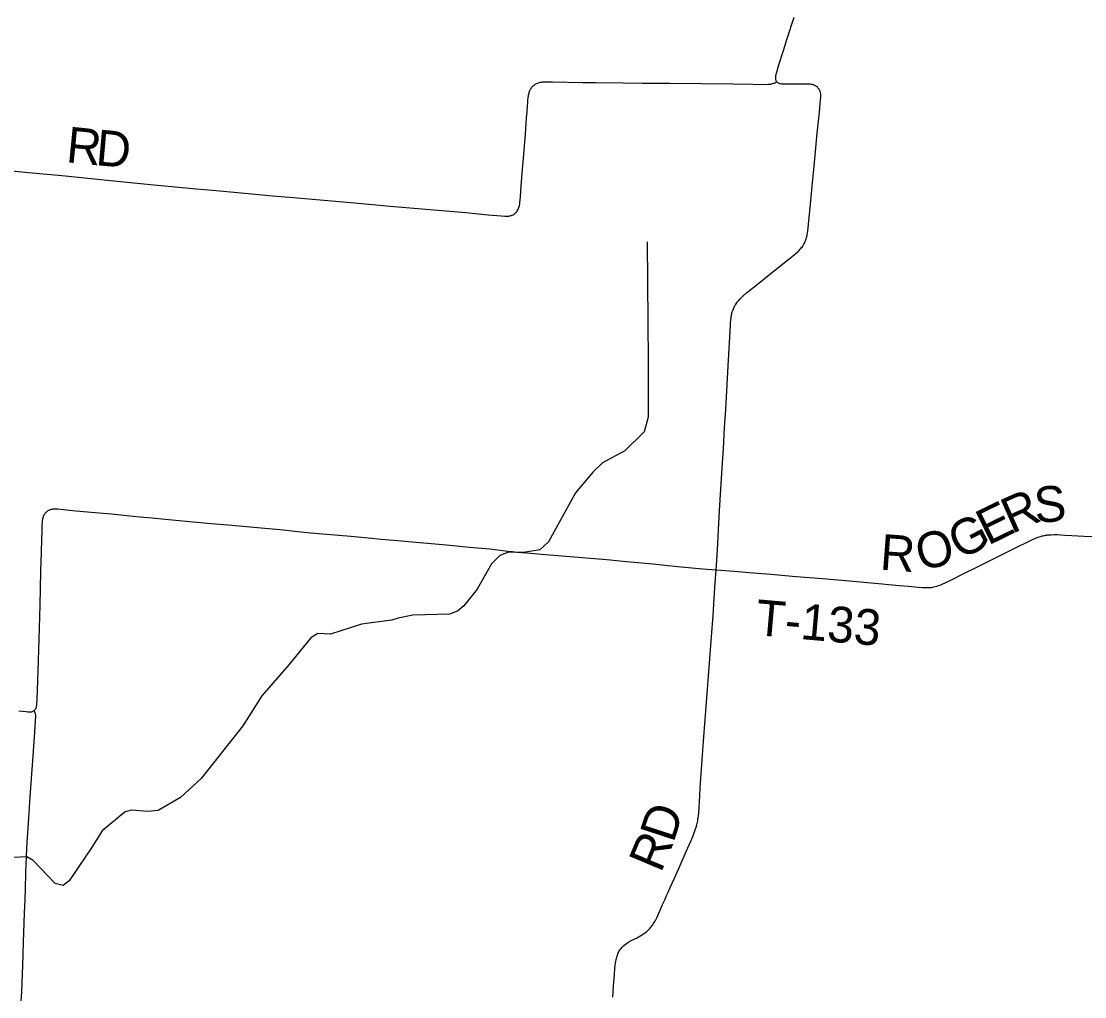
# Model space of a CAD drawing. Extents: x -49 to -8.2, y 9.4 to 23.5.
# Drawn here: x -43.371 to -42.527, y 19.456 to 20.23 of the extents above; entities that cross this region are included whole.
import ezdxf

# ---------------------------------------------------------------- set-up
doc = ezdxf.new("R2010")
doc.units = 0
for name, color, linetype in [('GM_X_County_Road', 7, 'Continuous'), ('GM_X_County_Road_Text', 7, 'Continuous'), ('GM_X_Major_River', 7, 'Continuous'), ('GM_X_Township_Road', 7, 'Continuous'), ('GM_X_Township_Road_Text', 7, 'Continuous')]:
    doc.layers.add(name, color=color, linetype=linetype)

msp = doc.modelspace()

# ---------------------------------------------------------------- linework, layer by layer
at = {"layer": 'GM_X_County_Road'}
for points in [[(-43.38957, 20.11204), (-43.36575, 20.10974), (-43.33915, 20.10727), (-43.29525, 20.10286), (-43.27947, 20.10135), (-43.26617, 20.10011), (-43.25194, 20.09874), (-43.23246, 20.0969), (-43.22596, 20.0963), (-43.2139, 20.09519), (-43.19689, 20.09352), (-43.1721, 20.09125), (-43.15852, 20.0901), (-43.13406, 20.08802), (-43.10404, 20.08536), (-43.07867, 20.08299), (-43.04709, 20.08036), (-43.0186, 20.07791), (-43.00066, 20.07628), (-42.99043, 20.07533), (-42.98763, 20.07512), (-42.98672, 20.07508), (-42.98578, 20.0751), (-42.98493, 20.07516), (-42.98425, 20.07524), (-42.98362, 20.07536), (-42.98296, 20.07551), (-42.98232, 20.07572), (-42.98158, 20.076), (-42.98101, 20.07628), (-42.98016, 20.07678), (-42.97946, 20.07731), (-42.97878, 20.07792), (-42.97837, 20.07837), (-42.97805, 20.07878), (-42.97761, 20.07937), (-42.97716, 20.08016), (-42.97673, 20.0811), (-42.97643, 20.0819), (-42.97618, 20.08274), (-42.97593, 20.08368), (-42.97572, 20.08472), (-42.97555, 20.08583), (-42.97516, 20.09018), (-42.97445, 20.09916), (-42.97343, 20.11249), (-42.97251, 20.12395), (-42.97124, 20.14006), (-42.97021, 20.15306), (-42.96985, 20.15771), (-42.9695, 20.16299), (-42.96939, 20.16486), (-42.96921, 20.16733), (-42.96903, 20.16891), (-42.96894, 20.16957), (-42.96884, 20.17023), (-42.96869, 20.17104), (-42.96849, 20.17202), (-42.96829, 20.17284), (-42.96809, 20.17346), (-42.9679, 20.17407), (-42.96763, 20.17475), (-42.96738, 20.17532), (-42.96705, 20.17592), (-42.96669, 20.17654), (-42.96627, 20.17713), (-42.9658, 20.17769), (-42.9653, 20.17821), (-42.96465, 20.17884), (-42.96409, 20.17929), (-42.96344, 20.17974), (-42.96287, 20.18008), (-42.96205, 20.18049), (-42.96128, 20.18079), (-42.9607, 20.181), (-42.95994, 20.18122), (-42.9592, 20.18139), (-42.95835, 20.18153), (-42.95758, 20.18163), (-42.95654, 20.1817), (-42.95531, 20.18174), (-42.94976, 20.18169), (-42.92615, 20.18116), (-42.91527, 20.18108), (-42.89352, 20.18091), (-42.8783, 20.18079), (-42.85655, 20.18062), (-42.83138, 20.18035), (-42.80653, 20.18007), (-42.79037, 20.17979), (-42.78167, 20.17971), (-42.77857, 20.17975), (-42.77764, 20.1798), (-42.77671, 20.17989), (-42.77608, 20.17999), (-42.77549, 20.18013), (-42.7749, 20.18032), (-42.77428, 20.18054), (-42.77369, 20.18077), (-42.77305, 20.18104), (-42.77232, 20.18139), (-42.77164, 20.18174)], [(-43.36132, 19.68272), (-43.36107, 19.68293), (-43.36074, 19.68321), (-43.36039, 19.68356), (-43.36008, 19.68395), (-43.35986, 19.68428), (-43.35965, 19.68463), (-43.3595, 19.685), (-43.35938, 19.68543), (-43.35929, 19.68584), (-43.35914, 19.68745), (-43.35894, 19.69181), (-43.3584, 19.70641), (-43.35785, 19.72256), (-43.35732, 19.73932), (-43.35654, 19.76635), (-43.35583, 19.79337), (-43.35531, 19.80858), (-43.355, 19.81852), (-43.35486, 19.82504), (-43.35477, 19.83032), (-43.35468, 19.83192), (-43.35455, 19.83321), (-43.35441, 19.83426), (-43.35424, 19.83522), (-43.35406, 19.83603), (-43.35387, 19.83662), (-43.35369, 19.83716), (-43.35348, 19.83767), (-43.35322, 19.83823), (-43.35291, 19.83874), (-43.35258, 19.83919), (-43.35219, 19.83966), (-43.3517, 19.8402), (-43.35124, 19.84059), (-43.35077, 19.84097), (-43.35026, 19.84133), (-43.34975, 19.84166), (-43.34929, 19.8419), (-43.34867, 19.84217), (-43.3481, 19.84236), (-43.3474, 19.84254), (-43.34664, 19.84266), (-43.34602, 19.84273), (-43.34528, 19.84278), (-43.34446, 19.84281), (-43.34343, 19.8428), (-43.34243, 19.84275), (-43.34035, 19.84256), (-43.33543, 19.84209), (-43.32824, 19.84137), (-43.31282, 19.83999), (-43.2998, 19.83876), (-43.28773, 19.83753), (-43.27752, 19.83655), (-43.26763, 19.8356), (-43.25712, 19.83455), (-43.24042, 19.83299), (-43.22072, 19.83124), (-43.20428, 19.8298), (-43.1896, 19.82849), (-43.1633, 19.82606), (-43.15183, 19.82491), (-43.14143, 19.82392), (-43.12878, 19.8228), (-43.10991, 19.82105), (-43.09599, 19.81978), (-43.08579, 19.81885), (-43.07249, 19.81766), (-43.05504, 19.81611), (-43.03387, 19.81422), (-43.01558, 19.81254), (-42.99935, 19.81102), (-42.98509, 19.80929), (-42.98141, 19.80888), (-42.97796, 19.80855), (-42.97, 19.80785), (-42.95836, 19.80692), (-42.92306, 19.80399), (-42.90666, 19.80252), (-42.89088, 19.80106), (-42.87015, 19.79912), (-42.85046, 19.79721), (-42.8304, 19.79523), (-42.81972, 19.79437)], [(-43.37331, 19.68243), (-43.36747, 19.6819), (-43.36611, 19.68177), (-43.365, 19.68169), (-43.36402, 19.68169), (-43.36353, 19.68175), (-43.36302, 19.68186), (-43.36257, 19.682), (-43.36216, 19.68218), (-43.36177, 19.68241), (-43.36132, 19.68272)]]:
    msp.add_lwpolyline(points, dxfattribs=at)
at = {"layer": 'GM_X_Major_River'}
msp.add_lwpolyline([(-42.87443, 20.05484), (-42.87369, 19.9595), (-42.87381, 19.91564), (-42.87688, 19.90393), (-42.89213, 19.88886), (-42.9101, 19.87935), (-42.91743, 19.87228), (-42.93138, 19.85547), (-42.95278, 19.8166), (-42.95972, 19.81028), (-42.97262, 19.80827), (-42.98473, 19.80833), (-42.99159, 19.80581), (-42.99815, 19.7991), (-43.00953, 19.77902), (-43.02019, 19.76575), (-43.025, 19.76167), (-43.03149, 19.75914), (-43.06063, 19.75841), (-43.07222, 19.75598), (-43.07736, 19.75457), (-43.10145, 19.75126), (-43.12582, 19.7434), (-43.13602, 19.7438), (-43.14158, 19.7405), (-43.15903, 19.71901), (-43.18052, 19.69457), (-43.19556, 19.67057), (-43.22855, 19.62889), (-43.24493, 19.61384), (-43.26273, 19.60357), (-43.27126, 19.60261), (-43.28373, 19.60381), (-43.28886, 19.60239), (-43.30732, 19.5872), (-43.31631, 19.57295), (-43.32021, 19.56714), (-43.33346, 19.54766), (-43.33827, 19.54396), (-43.34448, 19.5456), (-43.36208, 19.56381), (-43.36695, 19.56657), (-43.39289, 19.56538)], dxfattribs=at)
at = {"layer": 'GM_X_Township_Road'}
for points in [[(-42.77164, 20.18174), (-42.77193, 20.18213), (-42.77214, 20.18256), (-42.77228, 20.18295), (-42.77239, 20.18342), (-42.77246, 20.18386), (-42.77249, 20.18453), (-42.77248, 20.1851), (-42.77245, 20.18558), (-42.77237, 20.18618), (-42.77229, 20.18664), (-42.77164, 20.18936), (-42.77016, 20.19443), (-42.76634, 20.20658), (-42.76335, 20.21606), (-42.75794, 20.23292)], [(-42.81972, 19.79437), (-42.81898, 19.80609), (-42.81828, 19.81998), (-42.81796, 19.82618), (-42.81709, 19.84138), (-42.81653, 19.85006), (-42.8157, 19.86308), (-42.81505, 19.87517), (-42.81406, 19.89068), (-42.81304, 19.90742), (-42.81221, 19.92168), (-42.81011, 19.95641), (-42.80913, 19.97471), (-42.80849, 19.98869), (-42.80831, 19.99082), (-42.80811, 19.99282), (-42.80794, 19.99424), (-42.80777, 19.99548), (-42.80765, 19.99625), (-42.80753, 19.99687), (-42.80736, 19.99758), (-42.8072, 19.99831), (-42.80698, 19.99912), (-42.80664, 20.00013), (-42.80638, 20.00085), (-42.80611, 20.00155), (-42.80574, 20.00239), (-42.80543, 20.00299), (-42.8051, 20.00361), (-42.80477, 20.00418), (-42.80437, 20.00482), (-42.80391, 20.00552), (-42.80323, 20.00646), (-42.80263, 20.00727), (-42.8008, 20.00939), (-42.79837, 20.0118), (-42.79556, 20.01426), (-42.79195, 20.01721), (-42.78857, 20.01994), (-42.77468, 20.03093), (-42.76179, 20.04117), (-42.75639, 20.04557), (-42.75473, 20.04709), (-42.75388, 20.04791), (-42.75323, 20.04857), (-42.75272, 20.04917), (-42.75216, 20.04985), (-42.75157, 20.05062), (-42.75107, 20.05135), (-42.75072, 20.05194), (-42.75019, 20.05282), (-42.74974, 20.05365), (-42.74933, 20.05447), (-42.74906, 20.05509), (-42.74886, 20.0556), (-42.74857, 20.05634), (-42.74829, 20.05708), (-42.74798, 20.05807), (-42.74776, 20.05889), (-42.74756, 20.05975), (-42.7474, 20.06068), (-42.74725, 20.0616), (-42.74699, 20.06349), (-42.74666, 20.06591), (-42.74585, 20.07426), (-42.74519, 20.08169), (-42.74361, 20.09901), (-42.74208, 20.11478), (-42.73956, 20.14106), (-42.73779, 20.15774), (-42.73713, 20.16456), (-42.7368, 20.16772), (-42.73664, 20.1699), (-42.73663, 20.17058), (-42.73663, 20.1712), (-42.73667, 20.17177), (-42.73673, 20.17231), (-42.73693, 20.1732), (-42.73708, 20.17376), (-42.73725, 20.17428), (-42.73743, 20.17477), (-42.73765, 20.17523), (-42.73805, 20.17586), (-42.73835, 20.17629), (-42.73866, 20.17668), (-42.73899, 20.17705), (-42.73936, 20.17739), (-42.74002, 20.17789), (-42.7406, 20.17829), (-42.74117, 20.17864), (-42.74168, 20.17889), (-42.7424, 20.17923), (-42.74288, 20.17939), (-42.74335, 20.17954), (-42.74386, 20.17964), (-42.74431, 20.1797), (-42.7452, 20.17976), (-42.74683, 20.17981), (-42.74963, 20.17985), (-42.75616, 20.17989), (-42.76179, 20.17985), (-42.76533, 20.17989), (-42.76727, 20.17997), (-42.76805, 20.18005), (-42.76875, 20.18016), (-42.7693, 20.18026), (-42.76972, 20.18038), (-42.77021, 20.18059), (-42.77062, 20.1808), (-42.77103, 20.1811), (-42.77134, 20.18137), (-42.77164, 20.18174)], [(-42.81972, 19.79437), (-42.80521, 19.7933), (-42.7935, 19.79236), (-42.77635, 19.79092), (-42.75628, 19.78915), (-42.73538, 19.78743), (-42.714, 19.78558), (-42.69678, 19.7841), (-42.68789, 19.7833), (-42.67455, 19.78212), (-42.66717, 19.78145), (-42.65934, 19.78077), (-42.65585, 19.78052), (-42.654, 19.78044), (-42.65247, 19.78038), (-42.65104, 19.78036), (-42.65037, 19.78038), (-42.64982, 19.78042), (-42.64926, 19.78048), (-42.64881, 19.78054), (-42.64809, 19.78066), (-42.647, 19.78091), (-42.64467, 19.78154), (-42.64311, 19.782), (-42.64143, 19.7826), (-42.63983, 19.7833), (-42.63803, 19.78413), (-42.63133, 19.78741), (-42.62517, 19.79036), (-42.61124, 19.79724), (-42.59155, 19.80717), (-42.58154, 19.81216), (-42.57179, 19.81698), (-42.56869, 19.81846), (-42.56663, 19.81936), (-42.56499, 19.82004), (-42.56418, 19.82035), (-42.56329, 19.82066), (-42.56219, 19.821), (-42.56099, 19.82133), (-42.56017, 19.82154), (-42.55917, 19.82177), (-42.55822, 19.82195), (-42.55736, 19.82207), (-42.55658, 19.82216), (-42.55536, 19.82224), (-42.55385, 19.82232), (-42.55143, 19.8224), (-42.54876, 19.82236), (-42.54604, 19.82224), (-42.543, 19.82207), (-42.53748, 19.82176), (-42.52788, 19.82126), (-42.51765, 19.82084)], [(-42.9018, 19.45542), (-42.90115, 19.4644), (-42.90056, 19.47308), (-42.90014, 19.47824), (-42.89987, 19.48067), (-42.89963, 19.48231), (-42.89938, 19.48371), (-42.89913, 19.48506), (-42.89889, 19.48609), (-42.89868, 19.48692), (-42.89839, 19.48786), (-42.89807, 19.4888), (-42.89778, 19.48958), (-42.89745, 19.49045), (-42.89712, 19.49119), (-42.89671, 19.49197), (-42.89622, 19.49279), (-42.89576, 19.49345), (-42.89527, 19.49402), (-42.89457, 19.49476), (-42.89383, 19.4955), (-42.89301, 19.49629), (-42.89207, 19.49707), (-42.89104, 19.49785), (-42.89021, 19.49842), (-42.88909, 19.49911), (-42.88665, 19.50045), (-42.88301, 19.50222), (-42.87944, 19.50412), (-42.87661, 19.50603), (-42.87513, 19.50713), (-42.87419, 19.50796), (-42.87336, 19.50878), (-42.87254, 19.50969), (-42.87184, 19.51046), (-42.87123, 19.51124), (-42.87061, 19.51207), (-42.87008, 19.51281), (-42.86947, 19.51374), (-42.86893, 19.51458), (-42.8685, 19.51533), (-42.86798, 19.51622), (-42.86744, 19.5172), (-42.86688, 19.51832), (-42.86605, 19.52008), (-42.86519, 19.52195), (-42.86339, 19.52624), (-42.86224, 19.52879), (-42.86037, 19.53305), (-42.85882, 19.53644), (-42.85756, 19.53928), (-42.85616, 19.5424), (-42.85315, 19.54922), (-42.84949, 19.55745), (-42.84349, 19.57077), (-42.83966, 19.5796), (-42.83832, 19.58275), (-42.83717, 19.58563), (-42.83632, 19.58797), (-42.83606, 19.58876), (-42.83585, 19.58942), (-42.83563, 19.59012), (-42.83544, 19.5908), (-42.83526, 19.59143), (-42.83511, 19.59209), (-42.83484, 19.59322), (-42.83464, 19.59419), (-42.83443, 19.5953), (-42.83429, 19.59611), (-42.83419, 19.59692), (-42.8341, 19.5976), (-42.8339, 19.5992), (-42.83361, 19.60194), (-42.83331, 19.60565), (-42.83277, 19.61503), (-42.83234, 19.62147), (-42.83134, 19.63618), (-42.83001, 19.65494), (-42.82823, 19.6791), (-42.82616, 19.70668), (-42.82348, 19.74137), (-42.82225, 19.7581), (-42.82071, 19.78042), (-42.81972, 19.79437)], [(-43.37141, 19.45242), (-43.37104, 19.45933), (-43.37067, 19.46677), (-43.37017, 19.48074), (-43.36986, 19.48943), (-43.36959, 19.49904), (-43.36887, 19.52202), (-43.36844, 19.53288), (-43.36814, 19.54095), (-43.36784, 19.5543), (-43.36764, 19.56051), (-43.36736, 19.56705), (-43.36712, 19.57297), (-43.36679, 19.57839), (-43.36545, 19.59743), (-43.36435, 19.61417), (-43.36203, 19.6467), (-43.36073, 19.66561), (-43.36005, 19.67489), (-43.35991, 19.67788), (-43.35991, 19.67854), (-43.35993, 19.67901), (-43.35997, 19.67942), (-43.36006, 19.67983), (-43.36017, 19.68016), (-43.3607, 19.68135), (-43.36132, 19.68272)]]:
    msp.add_lwpolyline(points, dxfattribs=at)

# ---------------------------------------------------------------- texts
at = {"layer": 'GM_X_County_Road_Text'}
for s, rotation, p in [('R', 354.40592, (-43.33645, 20.11796)), ('D', 354.89098, (-43.31297, 20.11566))]:
    msp.add_text(s, height=0.02841, rotation=rotation, dxfattribs=at).set_placement(p)
at = {"layer": 'GM_X_Township_Road_Text'}
for s, height, rotation, p in [('S', 0.02841, 4.42786, (-42.56627, 19.83154)), ('R', 0.02841, 23.87253, (-42.58515, 19.82272)), ('E', 0.02841, 26.17216, (-42.60395, 19.81347)), ('G', 0.02841, 27.5723, (-42.62595, 19.80198)), ('O', 0.02841, 13.11401, (-42.65761, 19.7936)), ('R', 0.02841, 355.68302, (-42.69026, 19.79463)), ('T-133', 0.028409, 354.95727, (-42.78917, 19.74274)), ('D', 0.02841, 71.93156, (-42.85377, 19.57712)), ('R', 0.02841, 67.24623, (-42.86367, 19.55327))]:
    msp.add_text(s, height=height, rotation=rotation, dxfattribs=at).set_placement(p)

doc.saveas('drawing.dxf')
